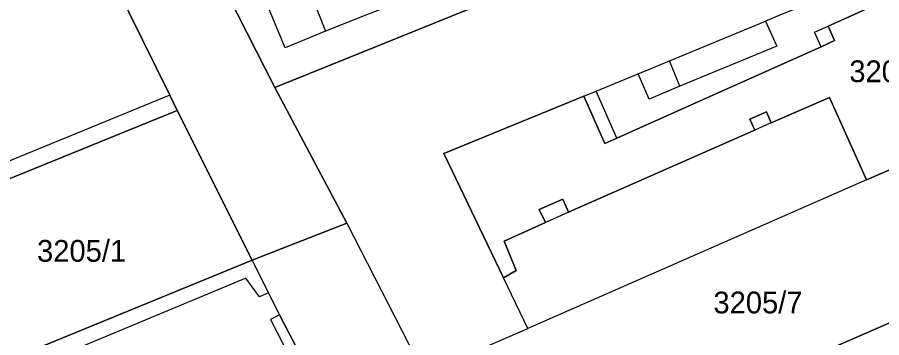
# Model space of a CAD drawing. Extents: x -264070 to -262271, y -1238894 to -1238141.
# Drawn here: x -262992.9 to -262913.5, y -1238643.9 to -1238614.4 of the extents above; entities that cross this region are included whole.
import ezdxf

# ---------------------------------------------------------------- set-up
doc = ezdxf.new("R2010")
doc.units = 0
for name, color, linetype in [('body_kn', 7, 'Continuous'), ('kladpar_druhypozemkov', 7, 'Continuous'), ('kladpar_hranice', 7, 'Continuous'), ('kladpar_parcelnecisla', 7, 'Continuous'), ('kladpar_plochy', 7, 'Continuous'), ('zappar_hrandruhpozemk', 7, 'Continuous')]:
    doc.layers.add(name, color=color, linetype=linetype)

msp = doc.modelspace()

# ---------------------------------------------------------------- linework, layer by layer
at = {"layer": 'body_kn'}
for p, q in [((-262924.19, -1238614.78), (-262924.19, -1238614.78)), ((-262924.19, -1238614.78), (-262924.19, -1238614.78)), ((-262964.57, -1238615.71), (-262964.57, -1238615.71)), ((-262919.68, -1238615.81), (-262919.68, -1238615.81)), ((-262918.44, -1238615.25), (-262918.44, -1238615.25)), ((-262917.84, -1238616.56), (-262917.84, -1238616.56)), ((-262968.28, -1238617.22), (-262968.28, -1238617.22)), ((-262923.15, -1238617.08), (-262923.15, -1238617.08)), ((-262919.08, -1238617.13), (-262919.08, -1238617.13)), ((-262919.08, -1238617.13), (-262919.08, -1238617.13)), ((-262932.98, -1238618.42), (-262932.98, -1238618.42)), ((-262935.88, -1238619.62), (-262935.88, -1238619.62)), ((-262935.88, -1238619.62), (-262935.88, -1238619.62)), ((-262937.58, -1238620.32), (-262937.58, -1238620.32)), ((-262969.23, -1238620.88), (-262969.23, -1238620.88)), ((-262939.74, -1238621.21), (-262939.74, -1238621.21)), ((-262932.03, -1238620.77), (-262932.03, -1238620.77)), ((-262928.2, -1238621.22), (-262928.2, -1238621.22)), ((-262978.88, -1238621.59), (-262978.88, -1238621.59)), ((-262978.88, -1238621.59), (-262978.88, -1238621.59)), ((-262940.85, -1238621.66), (-262940.85, -1238621.66)), ((-262940.85, -1238621.66), (-262940.85, -1238621.66)), ((-262934.87, -1238621.94), (-262934.87, -1238621.94)), ((-262934.87, -1238621.94), (-262934.87, -1238621.94)), ((-262918.29, -1238621.79), (-262918.29, -1238621.79)), ((-262978.2, -1238622.99), (-262978.2, -1238622.99)), ((-262978.2, -1238622.99), (-262978.2, -1238622.99)), ((-262924.08, -1238623.1), (-262924.08, -1238623.1)), ((-262925.61, -1238623.78), (-262925.61, -1238623.78)), ((-262924.08, -1238624.3), (-262924.08, -1238624.3)), ((-262923.65, -1238624.12), (-262923.65, -1238624.12)), ((-262923.65, -1238624.12), (-262923.65, -1238624.12)), ((-262925.3, -1238624.86), (-262925.3, -1238624.86)), ((-262925.17, -1238624.8), (-262925.17, -1238624.8)), ((-262938.93, -1238626.03), (-262938.93, -1238626.03)), ((-262937.82, -1238625.53), (-262937.82, -1238625.53)), ((-262937.82, -1238625.53), (-262937.82, -1238625.53)), ((-262953.71, -1238626.95), (-262953.71, -1238626.95)), ((-262914.9, -1238629.37), (-262914.9, -1238629.37)), ((-262914.9, -1238629.37), (-262914.9, -1238629.37)), ((-262942.8, -1238631.14), (-262942.8, -1238631.14)), ((-262944.95, -1238632.08), (-262944.95, -1238632.08)), ((-262942.28, -1238632.33), (-262942.28, -1238632.33)), ((-262942.28, -1238632.33), (-262942.28, -1238632.33)), ((-262942.2, -1238632.3), (-262942.2, -1238632.3)), ((-262962.63, -1238633.33), (-262962.63, -1238633.33)), ((-262962.63, -1238633.33), (-262962.63, -1238633.33)), ((-262944.37, -1238633.27), (-262944.37, -1238633.27)), ((-262943.95, -1238633.08), (-262943.95, -1238633.08)), ((-262948.18, -1238634.99), (-262948.18, -1238634.99)), ((-262971.32, -1238636.73), (-262971.32, -1238636.73)), ((-262971.32, -1238636.73), (-262971.32, -1238636.73)), ((-262947.06, -1238637.67), (-262947.06, -1238637.67)), ((-262971.88, -1238638.4), (-262971.88, -1238638.4)), ((-262948.23, -1238638.35), (-262948.23, -1238638.35)), ((-262969.81, -1238639.74), (-262969.81, -1238639.74)), ((-262969.81, -1238639.74), (-262969.81, -1238639.74)), ((-262970.64, -1238640.1), (-262970.64, -1238640.1)), ((-262968.79, -1238641.75), (-262968.79, -1238641.75)), ((-262968.79, -1238641.75), (-262968.79, -1238641.75)), ((-262969.61, -1238642.18), (-262969.61, -1238642.18)), ((-262946.01, -1238643), (-262946.01, -1238643)), ((-262946.01, -1238643), (-262946.01, -1238643))]:
    msp.add_line(p, q, dxfattribs=at)
at = {"layer": 'kladpar_druhypozemkov'}
for p, q in [((-262986.84, -1238634.8), (-262986.84, -1238634.8)), ((-262924.03, -1238639.45), (-262924.03, -1238639.45))]:
    msp.add_line(p, q, dxfattribs=at)
at = {"layer": 'kladpar_hranice'}
for points in [[(-262960.21, -1238589.66), (-262959.39, -1238591.38), (-262957.89, -1238594.66), (-262956.39, -1238598.05), (-262956.3, -1238598.3), (-262955.85, -1238599.27), (-262949.83, -1238613.04), (-262969.23, -1238620.88), (-262980.41, -1238598.9), (-262976.99, -1238597.37), (-262960.21, -1238589.66)], [(-262980.41, -1238598.9), (-262969.23, -1238620.88), (-262962.63, -1238633.33), (-262971.32, -1238636.73)], [(-262978.88, -1238621.59), (-262978.2, -1238622.99), (-262993.97, -1238629.43), (-262996.2, -1238630.39), (-263000.97, -1238632.43), (-263003.89, -1238633.64), (-263026.91, -1238643.19), (-263027.76, -1238641.45), (-263035, -1238626.43), (-263034.44, -1238626.17), (-263033.61, -1238625.79), (-263029.46, -1238623.89), (-263013.62, -1238616.66), (-263010.26, -1238615.11), (-262996.87, -1238608.96), (-262992.82, -1238607.1), (-262991.87, -1238609.12), (-262989.54, -1238608.02), (-262990.49, -1238606.03), (-262988.27, -1238605.01), (-262987.48, -1238606.76), (-262986.41, -1238606.26), (-262978.88, -1238621.59)], [(-262971.32, -1238636.73), (-262978.2, -1238622.99), (-262978.88, -1238621.59), (-262986.41, -1238606.26)], [(-262896.4, -1238635.32), (-262949.65, -1238658.59), (-262942.14, -1238673.1), (-262940.73, -1238675.81), (-262939.53, -1238678.14), (-262938.79, -1238679.58), (-262947.42, -1238683.01), (-262947.65, -1238682.57), (-262948.59, -1238680.74), (-262948.95, -1238680.03), (-262950.35, -1238677.31), (-262968.79, -1238641.75), (-262969.81, -1238639.74), (-262971.32, -1238636.73), (-262962.63, -1238633.33), (-262969.23, -1238620.88), (-262949.83, -1238613.04)], [(-262909.94, -1238627.21), (-262914.9, -1238629.37), (-262918.29, -1238621.79), (-262923.65, -1238624.12), (-262924.08, -1238623.1), (-262925.61, -1238623.78), (-262925.17, -1238624.8), (-262925.3, -1238624.86), (-262942.2, -1238632.3), (-262942.28, -1238632.33), (-262942.8, -1238631.14), (-262944.95, -1238632.08), (-262944.37, -1238633.27), (-262948.18, -1238634.99), (-262947.06, -1238637.67), (-262948.23, -1238638.35), (-262953.71, -1238626.95), (-262940.85, -1238621.66), (-262938.93, -1238626.03), (-262937.82, -1238625.53), (-262928.2, -1238621.22), (-262919.08, -1238617.13), (-262917.84, -1238616.56), (-262918.44, -1238615.25), (-262914.21, -1238613.35)], [(-262914.21, -1238613.35), (-262918.44, -1238615.25), (-262917.84, -1238616.56), (-262919.08, -1238617.13), (-262928.2, -1238621.22), (-262937.82, -1238625.53), (-262938.93, -1238626.03), (-262940.85, -1238621.66), (-262953.71, -1238626.95), (-262948.23, -1238638.35), (-262947.06, -1238637.67), (-262948.18, -1238634.99), (-262944.37, -1238633.27), (-262944.95, -1238632.08), (-262942.8, -1238631.14), (-262942.28, -1238632.33), (-262942.2, -1238632.3), (-262925.3, -1238624.86), (-262925.17, -1238624.8), (-262925.61, -1238623.78), (-262924.08, -1238623.1), (-262923.65, -1238624.12), (-262918.29, -1238621.79), (-262914.9, -1238629.37), (-262909.94, -1238627.21)], [(-262978.2, -1238622.99), (-262971.32, -1238636.73), (-262991.75, -1238645.12), (-262993.71, -1238645.98), (-262994.92, -1238646.51), (-262996.13, -1238647.01), (-262997.81, -1238647.72), (-262999.1, -1238648.26), (-263016.81, -1238655.62), (-263017.48, -1238655.9), (-263020.39, -1238657.1), (-263023.76, -1238649.66), (-263026.91, -1238643.19), (-263003.89, -1238633.64), (-263000.97, -1238632.43), (-262996.2, -1238630.39), (-262993.97, -1238629.43), (-262978.2, -1238622.99)], [(-262896.4, -1238635.32), (-262893.51, -1238640.81), (-262897.88, -1238642.99), (-262896.12, -1238646.52), (-262895.71, -1238646.31), (-262889.69, -1238657.71), (-262939.53, -1238678.14), (-262940.73, -1238675.81), (-262942.14, -1238673.1), (-262949.65, -1238658.59), (-262896.4, -1238635.32)], [(-262997.81, -1238647.72), (-262996.13, -1238647.01), (-262994.92, -1238646.51), (-262993.71, -1238645.98), (-262991.75, -1238645.12), (-262971.32, -1238636.73), (-262969.81, -1238639.74), (-262968.79, -1238641.75), (-262950.35, -1238677.31), (-262948.95, -1238680.03), (-262948.59, -1238680.74), (-262947.65, -1238682.57), (-262968.3, -1238690.84), (-262971.51, -1238692.13), (-262993.08, -1238700.78), (-263010.47, -1238667.87), (-263016.81, -1238655.62), (-262999.1, -1238648.26), (-262997.81, -1238647.72)]]:
    msp.add_lwpolyline(points, dxfattribs=at)
at = {"layer": 'kladpar_plochy'}
for p, q in [((-262986.41, -1238606.26), (-262978.88, -1238621.59)), ((-262978.88, -1238621.59), (-262978.2, -1238622.99)), ((-262978.2, -1238622.99), (-262993.97, -1238629.43)), ((-262991.75, -1238645.12), (-262971.32, -1238636.73)), ((-262971.32, -1238636.73), (-262969.81, -1238639.74)), ((-262969.81, -1238639.74), (-262968.79, -1238641.75)), ((-262968.79, -1238641.75), (-262950.35, -1238677.31))]:
    msp.add_line(p, q, dxfattribs=at)
for points in [[(-262960.21, -1238589.66), (-262959.39, -1238591.38), (-262957.89, -1238594.66), (-262956.39, -1238598.05), (-262956.3, -1238598.3), (-262955.85, -1238599.27), (-262949.83, -1238613.04), (-262969.23, -1238620.88), (-262980.41, -1238598.9), (-262976.99, -1238597.37)], [(-262978.2, -1238622.99), (-262971.32, -1238636.73), (-262991.75, -1238645.12), (-262993.71, -1238645.98), (-262994.92, -1238646.51), (-262996.13, -1238647.01), (-262997.81, -1238647.72), (-262999.1, -1238648.26), (-263016.81, -1238655.62), (-263017.48, -1238655.9), (-263020.39, -1238657.1), (-263023.76, -1238649.66), (-263026.91, -1238643.19), (-263003.89, -1238633.64), (-263000.97, -1238632.43), (-262996.2, -1238630.39), (-262993.97, -1238629.43)], [(-262896.4, -1238635.32), (-262893.51, -1238640.81), (-262897.88, -1238642.99), (-262896.12, -1238646.52), (-262895.71, -1238646.31), (-262889.69, -1238657.71), (-262939.53, -1238678.14), (-262940.73, -1238675.81), (-262942.14, -1238673.1), (-262949.65, -1238658.59)]]:
    msp.add_lwpolyline(points, close=True, dxfattribs=at)
for points in [[(-262980.41, -1238598.9), (-262969.23, -1238620.88), (-262962.63, -1238633.33), (-262971.32, -1238636.73), (-262978.2, -1238622.99), (-262978.88, -1238621.59), (-262986.41, -1238606.26)], [(-262896.4, -1238635.32), (-262949.65, -1238658.59), (-262942.14, -1238673.1), (-262940.73, -1238675.81), (-262939.53, -1238678.14), (-262938.79, -1238679.58), (-262947.42, -1238683.01), (-262947.65, -1238682.57), (-262948.59, -1238680.74), (-262948.95, -1238680.03), (-262950.35, -1238677.31), (-262968.79, -1238641.75), (-262969.81, -1238639.74), (-262971.32, -1238636.73), (-262962.63, -1238633.33), (-262969.23, -1238620.88), (-262949.83, -1238613.04)], [(-262909.94, -1238627.21), (-262914.9, -1238629.37), (-262918.29, -1238621.79), (-262923.65, -1238624.12), (-262924.08, -1238623.1), (-262925.61, -1238623.78), (-262925.17, -1238624.8), (-262925.3, -1238624.86), (-262942.2, -1238632.3), (-262942.28, -1238632.33), (-262942.8, -1238631.14), (-262944.95, -1238632.08), (-262944.37, -1238633.27), (-262948.18, -1238634.99), (-262947.06, -1238637.67), (-262948.23, -1238638.35), (-262953.71, -1238626.95), (-262940.85, -1238621.66), (-262938.93, -1238626.03), (-262937.82, -1238625.53), (-262928.2, -1238621.22), (-262919.08, -1238617.13), (-262917.84, -1238616.56), (-262918.44, -1238615.25), (-262914.21, -1238613.35)], [(-262914.21, -1238613.35), (-262918.44, -1238615.25), (-262917.84, -1238616.56), (-262919.08, -1238617.13), (-262928.2, -1238621.22), (-262937.82, -1238625.53), (-262938.93, -1238626.03), (-262940.85, -1238621.66), (-262953.71, -1238626.95), (-262948.23, -1238638.35), (-262947.06, -1238637.67), (-262948.18, -1238634.99), (-262944.37, -1238633.27), (-262944.95, -1238632.08), (-262942.8, -1238631.14), (-262942.28, -1238632.33), (-262942.2, -1238632.3), (-262925.3, -1238624.86), (-262925.17, -1238624.8), (-262925.61, -1238623.78), (-262924.08, -1238623.1), (-262923.65, -1238624.12), (-262918.29, -1238621.79), (-262914.9, -1238629.37), (-262909.94, -1238627.21)]]:
    msp.add_lwpolyline(points, dxfattribs=at)
at = {"layer": 'zappar_hrandruhpozemk'}
for p, q in [((-262967.1, -1238609.3), (-262964.57, -1238615.71)), ((-262924.19, -1238614.78), (-262923.15, -1238617.08)), ((-262919.68, -1238615.81), (-262918.44, -1238615.25)), ((-262919.08, -1238617.13), (-262919.68, -1238615.81)), ((-262923.15, -1238617.08), (-262932.03, -1238620.77)), ((-262932.03, -1238620.77), (-262932.98, -1238618.42)), ((-262934.87, -1238621.94), (-262935.88, -1238619.62)), ((-262937.82, -1238625.53), (-262939.74, -1238621.21)), ((-262932.03, -1238620.77), (-262934.87, -1238621.94)), ((-262978.88, -1238621.59), (-262994.57, -1238628.02)), ((-262914.9, -1238629.37), (-262946.01, -1238643)), ((-262962.63, -1238633.33), (-262955.55, -1238647.13)), ((-262971.88, -1238638.4), (-262991.16, -1238646.41)), ((-262946.01, -1238643), (-262948.23, -1238638.35)), ((-262968.79, -1238641.75), (-262969.61, -1238642.18)), ((-262969.61, -1238642.18), (-262951.72, -1238676.93)), ((-262955.55, -1238647.13), (-262946.01, -1238643))]:
    msp.add_line(p, q, dxfattribs=at)
for points in [[(-262959.06, -1238606.05), (-262955.44, -1238604.61), (-262952.98, -1238611.11), (-262956.61, -1238612.54), (-262960.55, -1238614.11), (-262964.57, -1238615.71), (-262968.28, -1238617.22), (-262970.93, -1238610.8)], [(-262915.22, -1238611.11), (-262922.85, -1238614.23), (-262924.19, -1238614.78)], [(-262935.88, -1238619.62), (-262932.98, -1238618.42), (-262924.19, -1238614.78)], [(-262940.85, -1238621.66), (-262939.74, -1238621.21), (-262937.58, -1238620.32), (-262935.88, -1238619.62)], [(-262923.65, -1238624.12), (-262924.08, -1238624.3), (-262925.17, -1238624.8)], [(-262942.28, -1238632.33), (-262943.95, -1238633.08), (-262944.37, -1238633.27)], [(-262969.81, -1238639.74), (-262970.64, -1238640.1), (-262971.88, -1238638.4)]]:
    msp.add_lwpolyline(points, dxfattribs=at)

# ---------------------------------------------------------------- texts
at = {"layer": 'kladpar_parcelnecisla'}
for s, p in [('3205/21', (-262916.484, -1238620.39)), ('3205/1', (-262991.056, -1238636.88)), ('3205/7', (-262928.958, -1238641.62))]:
    msp.add_text(s, height=2, dxfattribs=at).set_placement(p)

doc.saveas('drawing.dxf')
